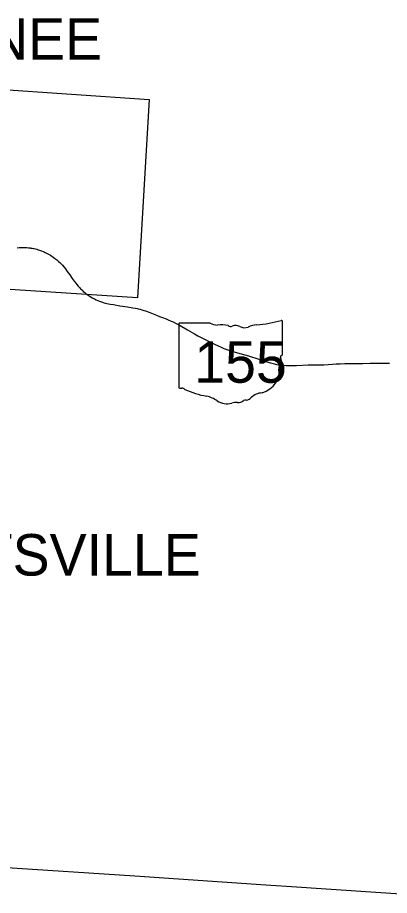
# Model space of a CAD drawing. Extents: x 1912787 to 2184787, y 543251 to 719251.
# Drawn here: x 2052262 to 2062306, y 567149 to 590845 of the extents above; entities that cross this region are included whole.
import ezdxf

# ---------------------------------------------------------------- set-up
doc = ezdxf.new("R2010")
doc.units = 0
for name, color, linetype in [('GM_X_Corporation', 7, 'Continuous'), ('GM_X_Corporation_Text', 7, 'Continuous'), ('GM_X_County', 7, 'Continuous'), ('GM_X_State_Location', 7, 'Continuous'), ('GM_X_State_Route', 7, 'Continuous'), ('GM_X_State_Shield', 7, 'Continuous')]:
    doc.layers.add(name, color=color, linetype=linetype)

msp = doc.modelspace()

# ---------------------------------------------------------------- linework, layer by layer
at = {"layer": 'GM_X_Corporation'}
msp.add_lwpolyline([(2046695, 589255), (2051466, 588927), (2051537, 588770), (2051611, 588917), (2055812, 588629), (2055502, 583278), (2051636, 583532), (2051604, 582944), (2051348, 582823), (2050727, 582317), (2050280, 582330), (2050353, 583524), (2049487, 583608), (2049464, 583762), (2049262, 583681), (2049194, 583529), (2048826, 583774), (2048758, 583888), (2048652, 583895), (2048644, 583801), (2046410, 584014)], close=True, dxfattribs=at)
at = {"layer": 'GM_X_County'}
msp.add_lwpolyline([(2063147, 567149), (2059524, 567388), (2058967, 567426), (2055429, 567669), (2051835, 567899), (2047163, 568214), (2046218, 568284), (2041578, 568579), (2040771, 568650), (2036775, 568919), (2035126, 569006), (2035208, 571601), (2035337, 575113), (2035458, 577483), (2035533, 579371), (2031578, 579662)], dxfattribs=at)
at = {"layer": 'GM_X_State_Route'}
for points in [[(2052252, 584633), (2052303, 584637), (2052346, 584639), (2052397, 584640), (2052462, 584638), (2052516, 584636), (2052560, 584631), (2052600, 584626), (2052623, 584623), (2052659, 584617), (2052691, 584611)], [(2052691, 584611), (2052707, 584607), (2052742, 584599), (2052779, 584589), (2052821, 584577), (2052856, 584566), (2052910, 584547), (2052950, 584530), (2052981, 584518), (2053012, 584503), (2053041, 584488), (2053079, 584470), (2053114, 584450), (2053149, 584430), (2053190, 584404), (2053227, 584378), (2053261, 584354), (2053313, 584313), (2053370, 584263), (2053403, 584233), (2053439, 584195), (2053472, 584158), (2053510, 584113), (2053553, 584058), (2053602, 583993), (2053672, 583897), (2053738, 583804), (2053795, 583725), (2053834, 583674), (2053861, 583639), (2053900, 583593), (2053941, 583548), (2053964, 583522), (2053988, 583501)], [(2053988, 583501), (2054007, 583483), (2054037, 583455), (2054075, 583422), (2054115, 583389), (2054156, 583360), (2054193, 583334), (2054238, 583306), (2054274, 583284), (2054337, 583250), (2054382, 583229), (2054430, 583209), (2054476, 583190), (2054527, 583173), (2054600, 583149), (2054676, 583130), (2054761, 583113), (2054856, 583096), (2055024, 583068), (2055235, 583034), (2055371, 583012), (2055451, 582998), (2055494, 582991), (2055519, 582985), (2055574, 582972), (2055622, 582958), (2055675, 582940), (2055716, 582925), (2055789, 582898), (2055921, 582848), (2056015, 582811), (2056096, 582779), (2056177, 582747), (2056276, 582709), (2056331, 582686), (2056409, 582653), (2056462, 582629), (2056530, 582596), (2056654, 582529), (2056849, 582418), (2057041, 582307), (2057134, 582255), (2057219, 582208), (2057296, 582170), (2057415, 582111), (2057585, 582031), (2057679, 581986), (2057759, 581949), (2057830, 581915), (2057915, 581881), (2058018, 581845), (2058138, 581811), (2058303, 581768), (2058404, 581742), (2058445, 581731), (2058460, 581727)], [(2058460, 581727), (2058500, 581715), (2058550, 581699), (2058720, 581643), (2058853, 581601), (2058998, 581556), (2059096, 581528), (2059203, 581497), (2059257, 581482), (2059299, 581474), (2059343, 581467), (2059377, 581464), (2059427, 581460), (2059518, 581455), (2059638, 581452), (2059793, 581453), (2060115, 581467), (2060536, 581474), (2060764, 581489), (2060866, 581494), (2060977, 581499), (2061100, 581503), (2061297, 581507), (2061584, 581510), (2061785, 581513), (2062005, 581516), (2062307, 581520)]]:
    msp.add_lwpolyline(points, dxfattribs=at)
at = {"layer": 'GM_X_State_Shield'}
for p, q in [((2056615, 582569), (2056615, 580868)), ((2057463, 582598), (2056642, 582598)), ((2059417, 581750), (2059417, 582640)), ((2059416, 581750), (2059417, 581750))]:
    msp.add_line(p, q, dxfattribs=at)
for centre, major_axis, start_param, end_param in [((2056647, 582572), (32.5, 0), 1.712693, 3.28349), ((2057658, 582796), (315, 0), 4.042523, 4.731795), ((2057763, 581643), (1130, 0), 1.404758, 1.657858), ((2058019, 582581), (90.8, 0), 3.836095, 5.185415), ((2058153, 582385), (189, 0), 0.950623, 2.079405), ((2058396, 582654), (227, 0), 4.081561, 5.145723), ((2058798, 582078), (598, 0), 1.699011, 2.107814), ((2058419, 584917), (2971, 0), 4.814394, 5.042369), ((2059386, 582644), (31.2, 0), 6.141152, 7.989035), ((2059383, 581747), (33.4, 0), 5.05454, 6.418171), ((2059528, 581378), (211, 0), 2.387724, 3.262537), ((2059409, 581685), (48.3, 0), 1.883978, 3.671073), ((2059102, 581572), (290, 0), 5.934695, 6.695948), ((2058585, 581265), (743, 0), 5.101752, 6.440018), ((2056647, 580864), (32.7, 0), 3.00124, 4.508301), ((2056652, 581038), (250, 0), 4.665946, 4.897461), ((2056703, 580769), (90.1, 0), 0.519207, 1.627899), ((2057841, 582298), (2146, 0), 4.195997, 4.488961), ((2057201, 580103), (671, 0), 0.823519, 1.323587), ((2058383, 580703), (240, 0), 4.937069, 5.64225), ((2058898, 580390), (407, 0), 1.647645, 2.488434), ((2057927, 580761), (426, 0), 4.026481, 4.996735), ((2058174, 580173), (350, 0), 1.495662, 1.94098), ((2058205, 580634), (227, 0), 4.691044, 5.507374), ((2058410, 580469), (63.9, 0), 1.147584, 2.315152)]:
    msp.add_ellipse(centre, major_axis=major_axis, ratio=0.8, start_param=start_param, end_param=end_param, dxfattribs=at)

# ---------------------------------------------------------------- texts
at = {"layer": 'GM_X_Corporation_Text'}
for s, p in [('SHAWNEE', (2046970, 589708)), ('STRAITSVILLE', (2046803, 575783))]:
    msp.add_text(s, height=1120, rotation=0, dxfattribs=at).set_placement(p)
at = {"layer": 'GM_X_State_Location'}
for s in ['s', 'r']:
    msp.add_text(s, height=1, dxfattribs=at).set_placement((2057465, 581970))
msp.add_text('155', height=1, rotation=0, dxfattribs=at).set_placement((2057112, 581897))
at = {"layer": 'GM_X_State_Shield'}
msp.add_text('155', height=1120.7, dxfattribs=at).set_placement((2057033, 580988))

doc.saveas('drawing.dxf')
